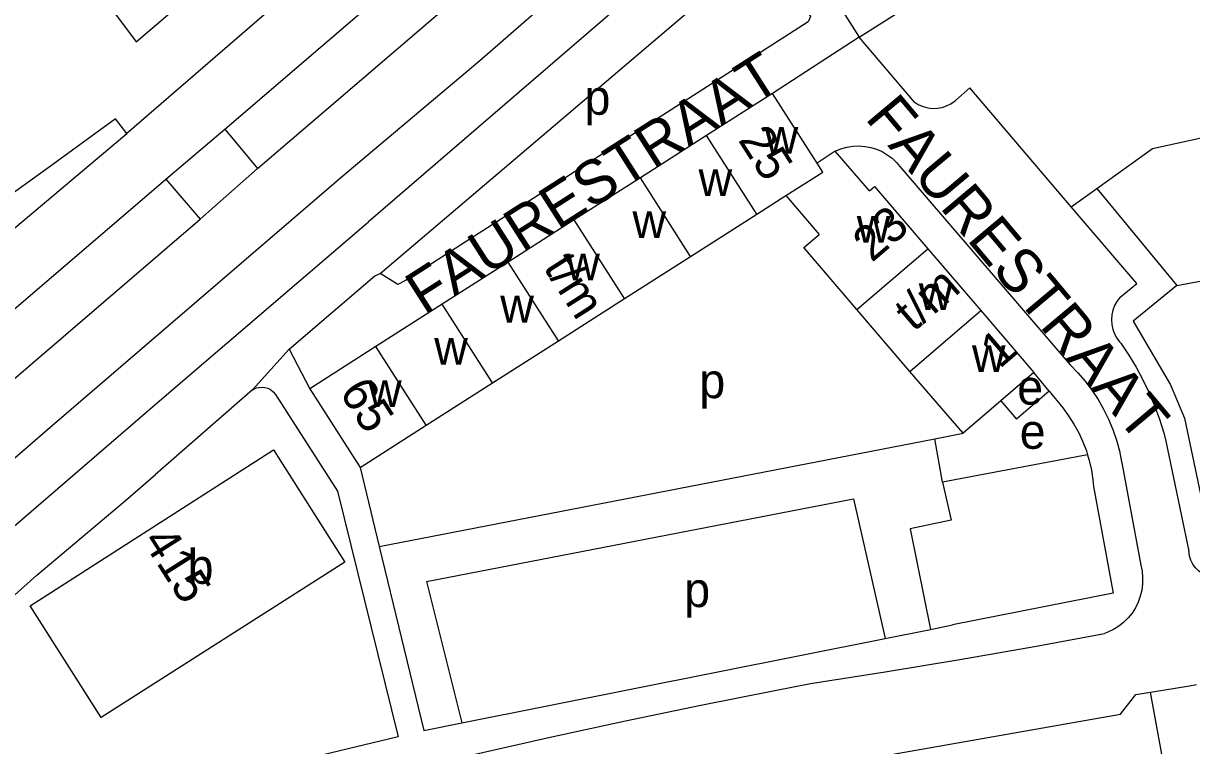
# Model space of a CAD drawing. Extents: x 159045 to 160918, y 380454 to 382516.
# Drawn here: x 159284.2 to 159418.5, y 381287.1 to 381370.2 of the extents above; entities that cross this region are included whole.
import ezdxf

# ---------------------------------------------------------------- set-up
doc = ezdxf.new("R2010")
doc.units = 0
for name, color, linetype in [('BLT_Basislijn', 7, 'Continuous'), ('BLT_Bebouwing', 7, 'Continuous'), ('BLT_Centroide', 7, 'Continuous'), ('BLT_Huisnummer', 7, 'Continuous'), ('BLT_Huisnummer_reeks', 7, 'Continuous'), ('BLT_Onderverdeling_panden', 7, 'Continuous'), ('BLT_Straatnaam', 7, 'Continuous')]:
    doc.layers.add(name, color=color, linetype=linetype)

msp = doc.modelspace()

# ---------------------------------------------------------------- linework, layer by layer
at = {"layer": 'BLT_Basislijn'}
for p, q in [((159297.18, 381368.08), (159352.04, 381415.11)), ((159368.14, 381385.53), (159323.87, 381347.36)), ((159321.67, 381379.72), (159296.09, 381357.55)), ((159380.31, 381368.62), (159370.34, 381362.15)), ((159386.67, 381361.14), (159380.31, 381368.62)), ((159282.73, 381346.25), (159296.09, 381357.55)), ((159300.57, 381352.29), (159307.36, 381358.05)), ((159307.36, 381358.05), (159311.14, 381353.53)), ((159304.53, 381347.69), (159311.14, 381353.53)), ((159384.97, 381353.75), (159404.56, 381330.94)), ((159276.05, 381331.28), (159300.57, 381352.29)), ((159286.99, 381323.51), (159320.72, 381352.46)), ((159300.57, 381352.29), (159304.53, 381347.69)), ((159404.67, 381349.11), (159407.62, 381351.22)), ((159407.62, 381351.22), (159416.81, 381340.04)), ((159271.81, 381319.6), (159304.53, 381347.69)), ((159416.81, 381340.04), (159445.22, 381345.45)), ((159416.81, 381340.04), (159411.79, 381335.94)), ((159411.79, 381335.94), (159416.08, 381328.63)), ((159314.77, 381332.73), (159310.53, 381328.05)), ((159314.77, 381332.73), (159317.14, 381328.19)), ((159402.12, 381327.91), (159400.38, 381330.06)), ((159310.53, 381328.05), (159299.39, 381318.32)), ((159402.12, 381327.91), (159398.37, 381324.67)), ((159402.12, 381327.91), (159403.69, 381325.98)), ((159396.56, 381326.79), (159398.37, 381324.67)), ((159264.84, 381304.38), (159286.99, 381323.51)), ((159325.12, 381310.06), (159388.98, 381322.44)), ((159388.98, 381322.44), (159392.23, 381323.07)), ((159389.89, 381317.44), (159388.98, 381322.44)), ((159415.56, 381322.16), (159418.19, 381309.49)), ((159406.55, 381320.58), (159389.89, 381317.44)), ((159410.49, 381319.66), (159412.66, 381307.89)), ((159322.92, 381319.14), (159325.12, 381310.06)), ((159330.54, 381306.02), (159379.64, 381315.54)), ((159379.64, 381315.54), (159383.28, 381299.48)), ((159330.54, 381306.02), (159334.6, 381289.76)), ((159383.28, 381299.48), (159388.48, 381300.51)), ((159388.48, 381300.51), (159391.04, 381301.02)), ((159334.6, 381289.76), (159383.28, 381299.48)), ((159413.77, 381293.29), (159418.27, 381294.01)), ((159418.27, 381294.01), (159419.09, 381294.16)), ((159415.1, 381286.15), (159413.77, 381293.29)), ((159327.29, 381288.14), (159317.55, 381285.81))]:
    msp.add_line(p, q, dxfattribs=at)
for points in [[(159307.36, 381358.05), (159340.5, 381386.49), (159366.49, 381408.71)], [(159311.14, 381353.53), (159343.29, 381381.06), (159369.52, 381403.52)], [(159320.72, 381352.46), (159336.68, 381365.92), (159352.14, 381379.44)], [(159325.21, 381341.42), (159364.78, 381375.11), (159369.2, 381378.78), (159369.65, 381378.86), (159374.68, 381371), (159374.42, 381370.36), (159328.13, 381340.62), (159327.27, 381340.17), (159325.21, 381341.42)], [(159290.19, 381377.3), (159292.74, 381374.04), (159297.18, 381368.08)], [(159404.67, 381349.11), (159393, 381362.78), (159391.37, 381361.32)], [(159386.67, 381361.14), (159387.14, 381360.85), (159387.65, 381360.63), (159388.18, 381360.49), (159388.73, 381360.42), (159389.28, 381360.43), (159389.82, 381360.53), (159390.35, 381360.7), (159390.84, 381360.94), (159391.37, 381361.32)], [(159407.62, 381351.22), (159414.02, 381355.8), (159442.67, 381362.09)], [(159296.09, 381357.55), (159294.81, 381359.24), (159287.18, 381353.66), (159283.07, 381350.72), (159276.5, 381347.1)], [(159377.55, 381355.49), (159378.19, 381355.76), (159378.86, 381355.95), (159379.55, 381356.07), (159380.24, 381356.1), (159380.93, 381356.05), (159381.62, 381355.93), (159382.28, 381355.73), (159382.92, 381355.45), (159383.52, 381355.1), (159384.07, 381354.68), (159384.58, 381354.21), (159384.97, 381353.75)], [(159410.25, 381338.67), (159412.23, 381340.27), (159404.67, 381349.11)], [(159260.14, 381291.83), (159268.35, 381299.66), (159299.58, 381326.57), (159323.87, 381347.36)], [(159314.77, 381332.73), (159324.62, 381341.17), (159325.21, 381341.42)], [(159410.25, 381338.67), (159409.91, 381338.23), (159409.64, 381337.74), (159409.45, 381337.22), (159409.33, 381336.67), (159409.29, 381336.11), (159409.33, 381335.56), (159409.45, 381335.01), (159409.64, 381334.49), (159409.91, 381334), (159410.24, 381333.56), (159410.37, 381333.42)], [(159410.37, 381333.42), (159411.29, 381332.06), (159412.14, 381330.65), (159412.92, 381329.21), (159413.62, 381327.73), (159414.26, 381326.22), (159414.82, 381324.67), (159415.31, 381323.11), (159415.56, 381322.16)], [(159404.56, 381330.94), (159405.45, 381330.02), (159406.28, 381329.04), (159407.05, 381328.01), (159407.76, 381326.94), (159408.39, 381325.83), (159408.96, 381324.67), (159409.45, 381323.49), (159409.87, 381322.28), (159410.21, 381321.04), (159410.47, 381319.78), (159410.49, 381319.66)], [(159310.53, 381328.05), (159310.74, 381328.16), (159310.99, 381328.27), (159311.3, 381328.34), (159311.64, 381328.37), (159311.96, 381328.33), (159312.3, 381328.24), (159312.62, 381328.08), (159312.94, 381327.84), (159313.18, 381327.54), (159320.33, 381316.4), (159327.29, 381288.14)], [(159416.08, 381328.63), (159417.68, 381324.79), (159421.58, 381306.41)], [(159403.69, 381325.98), (159404.37, 381325.07), (159404.99, 381324.12), (159405.54, 381323.12), (159406.01, 381322.09), (159406.42, 381321.03), (159406.55, 381320.58)], [(159406.55, 381320.58), (159406.74, 381319.94), (159406.99, 381318.83), (159407.16, 381317.71), (159407.24, 381316.94)], [(159281.31, 381302.78), (159285.75, 381306.73), (159295.96, 381315.33), (159299.39, 381318.32)], [(159389.89, 381317.44), (159390.85, 381313.06), (159386.16, 381312.06), (159388.48, 381300.51)], [(159407.24, 381316.94), (159409.49, 381304.67), (159391.04, 381301.02)], [(159325.12, 381310.06), (159330.24, 381288.89), (159334.6, 381289.76)], [(159421.58, 381306.41), (159421.17, 381306.42), (159420.66, 381306.51), (159420.18, 381306.68), (159419.72, 381306.92), (159419.31, 381307.23), (159418.95, 381307.6), (159418.65, 381308.02), (159418.42, 381308.48), (159418.27, 381308.98), (159418.19, 381309.49)], [(159412.66, 381307.89), (159412.81, 381307.19), (159412.88, 381306.47), (159412.87, 381305.75), (159412.78, 381305.03), (159412.61, 381304.33), (159412.37, 381303.65), (159412.05, 381303), (159411.66, 381302.39), (159411.21, 381301.83), (159410.7, 381301.32), (159410.13, 381300.87), (159409.52, 381300.49), (159408.87, 381300.18), (159408.51, 381300.04)], [(159374.68, 381294.29), (159383.28, 381295.63), (159391.86, 381297.05), (159400.43, 381298.55), (159408.51, 381300.04)], [(159302.35, 381277.68), (159310.37, 381279.81), (159318.94, 381282), (159327.53, 381284.12), (159336.15, 381286.16), (159344.78, 381288.12), (159353.42, 381290), (159362.09, 381291.81), (159370.77, 381293.53), (159374.68, 381294.29)], [(159373.07, 381284.21), (159410.34, 381290.77), (159412.1, 381293.03), (159413.77, 381293.29)]]:
    msp.add_lwpolyline(points, dxfattribs=at)
at = {"layer": 'BLT_Bebouwing'}
for p, q in [((159380.31, 381368.62), (159387.92, 381373.46)), ((159370.34, 381362.15), (159362.74, 381357.3)), ((159375.47, 381354.11), (159370.34, 381362.15)), ((159362.74, 381357.3), (159355.14, 381352.45)), ((159377.55, 381355.49), (159375.47, 381354.11)), ((159381.47, 381350.94), (159377.55, 381355.49)), ((159355.14, 381352.45), (159347.54, 381347.6)), ((159368.52, 381348.25), (159371.86, 381350.39)), ((159371.86, 381350.39), (159375.69, 381345.92)), ((159347.54, 381347.6), (159339.94, 381342.75)), ((159360.92, 381343.4), (159368.52, 381348.25)), ((159388.18, 381344.28), (159394.28, 381337.17)), ((159339.94, 381342.75), (159332.34, 381337.9)), ((159353.32, 381338.55), (159360.92, 381343.4)), ((159345.72, 381333.7), (159353.32, 381338.55)), ((159332.34, 381337.9), (159324.74, 381333.05)), ((159386.13, 381330.18), (159380.03, 381337.3)), ((159394.28, 381337.17), (159400.38, 381330.06)), ((159324.74, 381333.05), (159317.14, 381328.19)), ((159338.12, 381328.85), (159345.72, 381333.7)), ((159392.23, 381323.07), (159386.13, 381330.18)), ((159400.38, 381330.06), (159396.56, 381326.79)), ((159330.52, 381323.99), (159338.12, 381328.85)), ((159317.14, 381328.19), (159322.92, 381319.14)), ((159396.56, 381326.79), (159392.23, 381323.07)), ((159322.92, 381319.14), (159330.52, 381323.99)), ((159284.97, 381303.23), (159312.98, 381321.15)), ((159312.98, 381321.15), (159321.17, 381308.25)), ((159321.17, 381308.25), (159293.13, 381290.37))]:
    msp.add_line(p, q, dxfattribs=at)
for points in [[(159382.19, 381382.47), (159374.58, 381377.63), (159380.31, 381368.62)], [(159381.47, 381350.94), (159382.04, 381351.43), (159388.18, 381344.28)], [(159380.03, 381337.3), (159373.93, 381344.41), (159375.69, 381345.92)], [(159293.13, 381290.37), (159284.97, 381303.23)]]:
    msp.add_lwpolyline(points, dxfattribs=at)
at = {"layer": 'BLT_Onderverdeling_panden'}
for p, q in [((159368.52, 381348.25), (159362.74, 381357.3)), ((159360.92, 381343.4), (159355.14, 381352.45)), ((159353.32, 381338.55), (159347.54, 381347.6)), ((159380.03, 381337.3), (159388.18, 381344.28)), ((159345.72, 381333.7), (159339.94, 381342.75)), ((159338.12, 381328.85), (159332.34, 381337.9)), ((159386.13, 381330.18), (159394.28, 381337.17)), ((159330.52, 381323.99), (159324.74, 381333.05))]:
    msp.add_line(p, q, dxfattribs=at)
msp.add_lwpolyline([(159371.86, 381350.39), (159376.11, 381353.1), (159375.47, 381354.11)], dxfattribs=at)

# ---------------------------------------------------------------- texts
at = {"layer": 'BLT_Centroide'}
for s, p in [('p', (159348.72, 381359.69)), ('w', (159369.42, 381355.2)), ('w', (159361.83, 381350.34)), ('w', (159354.23, 381345.5)), ('w', (159380.02, 381344.97)), ('w', (159346.62, 381340.66)), ('w', (159387.15, 381337.22)), ('w', (159339.03, 381335.8)), ('w', (159331.44, 381330.94)), ('w', (159393.26, 381330.12)), ('p', (159361.92, 381327.1)), ('w', (159323.83, 381326.09)), ('e', (159398.46, 381326.36)), ('e', (159398.75, 381321.28)), ('b', (159303.09, 381305.75)), ('p', (159360.18, 381303.08))]:
    msp.add_text(s, height=4, dxfattribs=at).set_placement(p)
at = {"layer": 'BLT_Huisnummer'}
msp.add_text('415', height=4, rotation=302.331, dxfattribs=at).set_placement((159297.83, 381310.7))
at = {"layer": 'BLT_Huisnummer_reeks'}
for s, rotation, p in [('25', 302.5531, (159366.31, 381356.79)), ('23', 40.6175, (159381.75, 381342.63)), ('t/m', 302.5547, (159343.92, 381342.14)), ('t/m', 40.6135, (159386.54, 381334.65)), ('1', 40.6175, (159396.42, 381330.4)), ('65', 302.5563, (159320.46, 381327.79))]:
    msp.add_text(s, height=4, rotation=rotation, dxfattribs=at).set_placement(p)
at = {"layer": 'BLT_Straatnaam'}
for height, rotation, p in [(5, 32.5584, (159330.31, 381336.54)), (4.9999, 310.0322, (159380.87, 381359.27))]:
    msp.add_text('FAURESTRAAT', height=height, rotation=rotation, dxfattribs=at).set_placement(p)

doc.saveas('drawing.dxf')
